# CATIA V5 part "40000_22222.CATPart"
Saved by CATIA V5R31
Part number: 40000_22222
Revision: 1
Nomenclature: Kunckle RH
Property "部品番号(A社)": "40000_22222"
Property "部品名称(A社)": "Kunckle RH"
Property "Version(A社)": "1"
Property "材質(A社)": "FCD500"
Bounding box of the stored display mesh (mm): x 126.565 to 340.614, y 897.639 to 1013.2, z 1313.857 to 1558.404
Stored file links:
  \\solize.local\damia\dept\DDE_Design\10_order\2305701_JAMA_変換検証STEP3_お手本モデル作成\work\04_ダイハツ_鋳造\10_CATIA_V5\231219_案bCATIAデータ\40000_22222.CATPart
  \\solize.local\damia\dept\DDE_Design\10_order\2305701_JAMA_変換検証STEP3_お手本モデル作成\work\04_ダイハツ_鋳造\10_CATIA_V5\231130_案bCATIAデータ\40000_11111.CATPart
  G:\BODY\BX\_K_PROJECT\610_3D単独図\02_検討\79_自工会提出3D図面データ（ナックル改）\01_CATIA_DATA\PROPERTY_40000_22222.xls
  G:\BODY\BX\_K_PROJECT\610_3D単独図\02_検討\79_自工会提出3D図面データ（ナックル改）\01_CATIA_DATA\01_3D形状作画\WORK_AA_AA_230926.CATPart
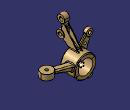
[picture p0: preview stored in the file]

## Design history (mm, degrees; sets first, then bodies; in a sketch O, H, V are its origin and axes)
Set1 "40000_22222"
  Line1 to Line3: stored without definition
  TriDim1
Body1 (main body)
